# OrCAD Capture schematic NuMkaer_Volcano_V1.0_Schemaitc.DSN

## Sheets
1 Nu-Link2-Me: size A3; title: Nu-Link2-Me; rev: 1.0; company: CMHuang; note: Nu-Link2-Me
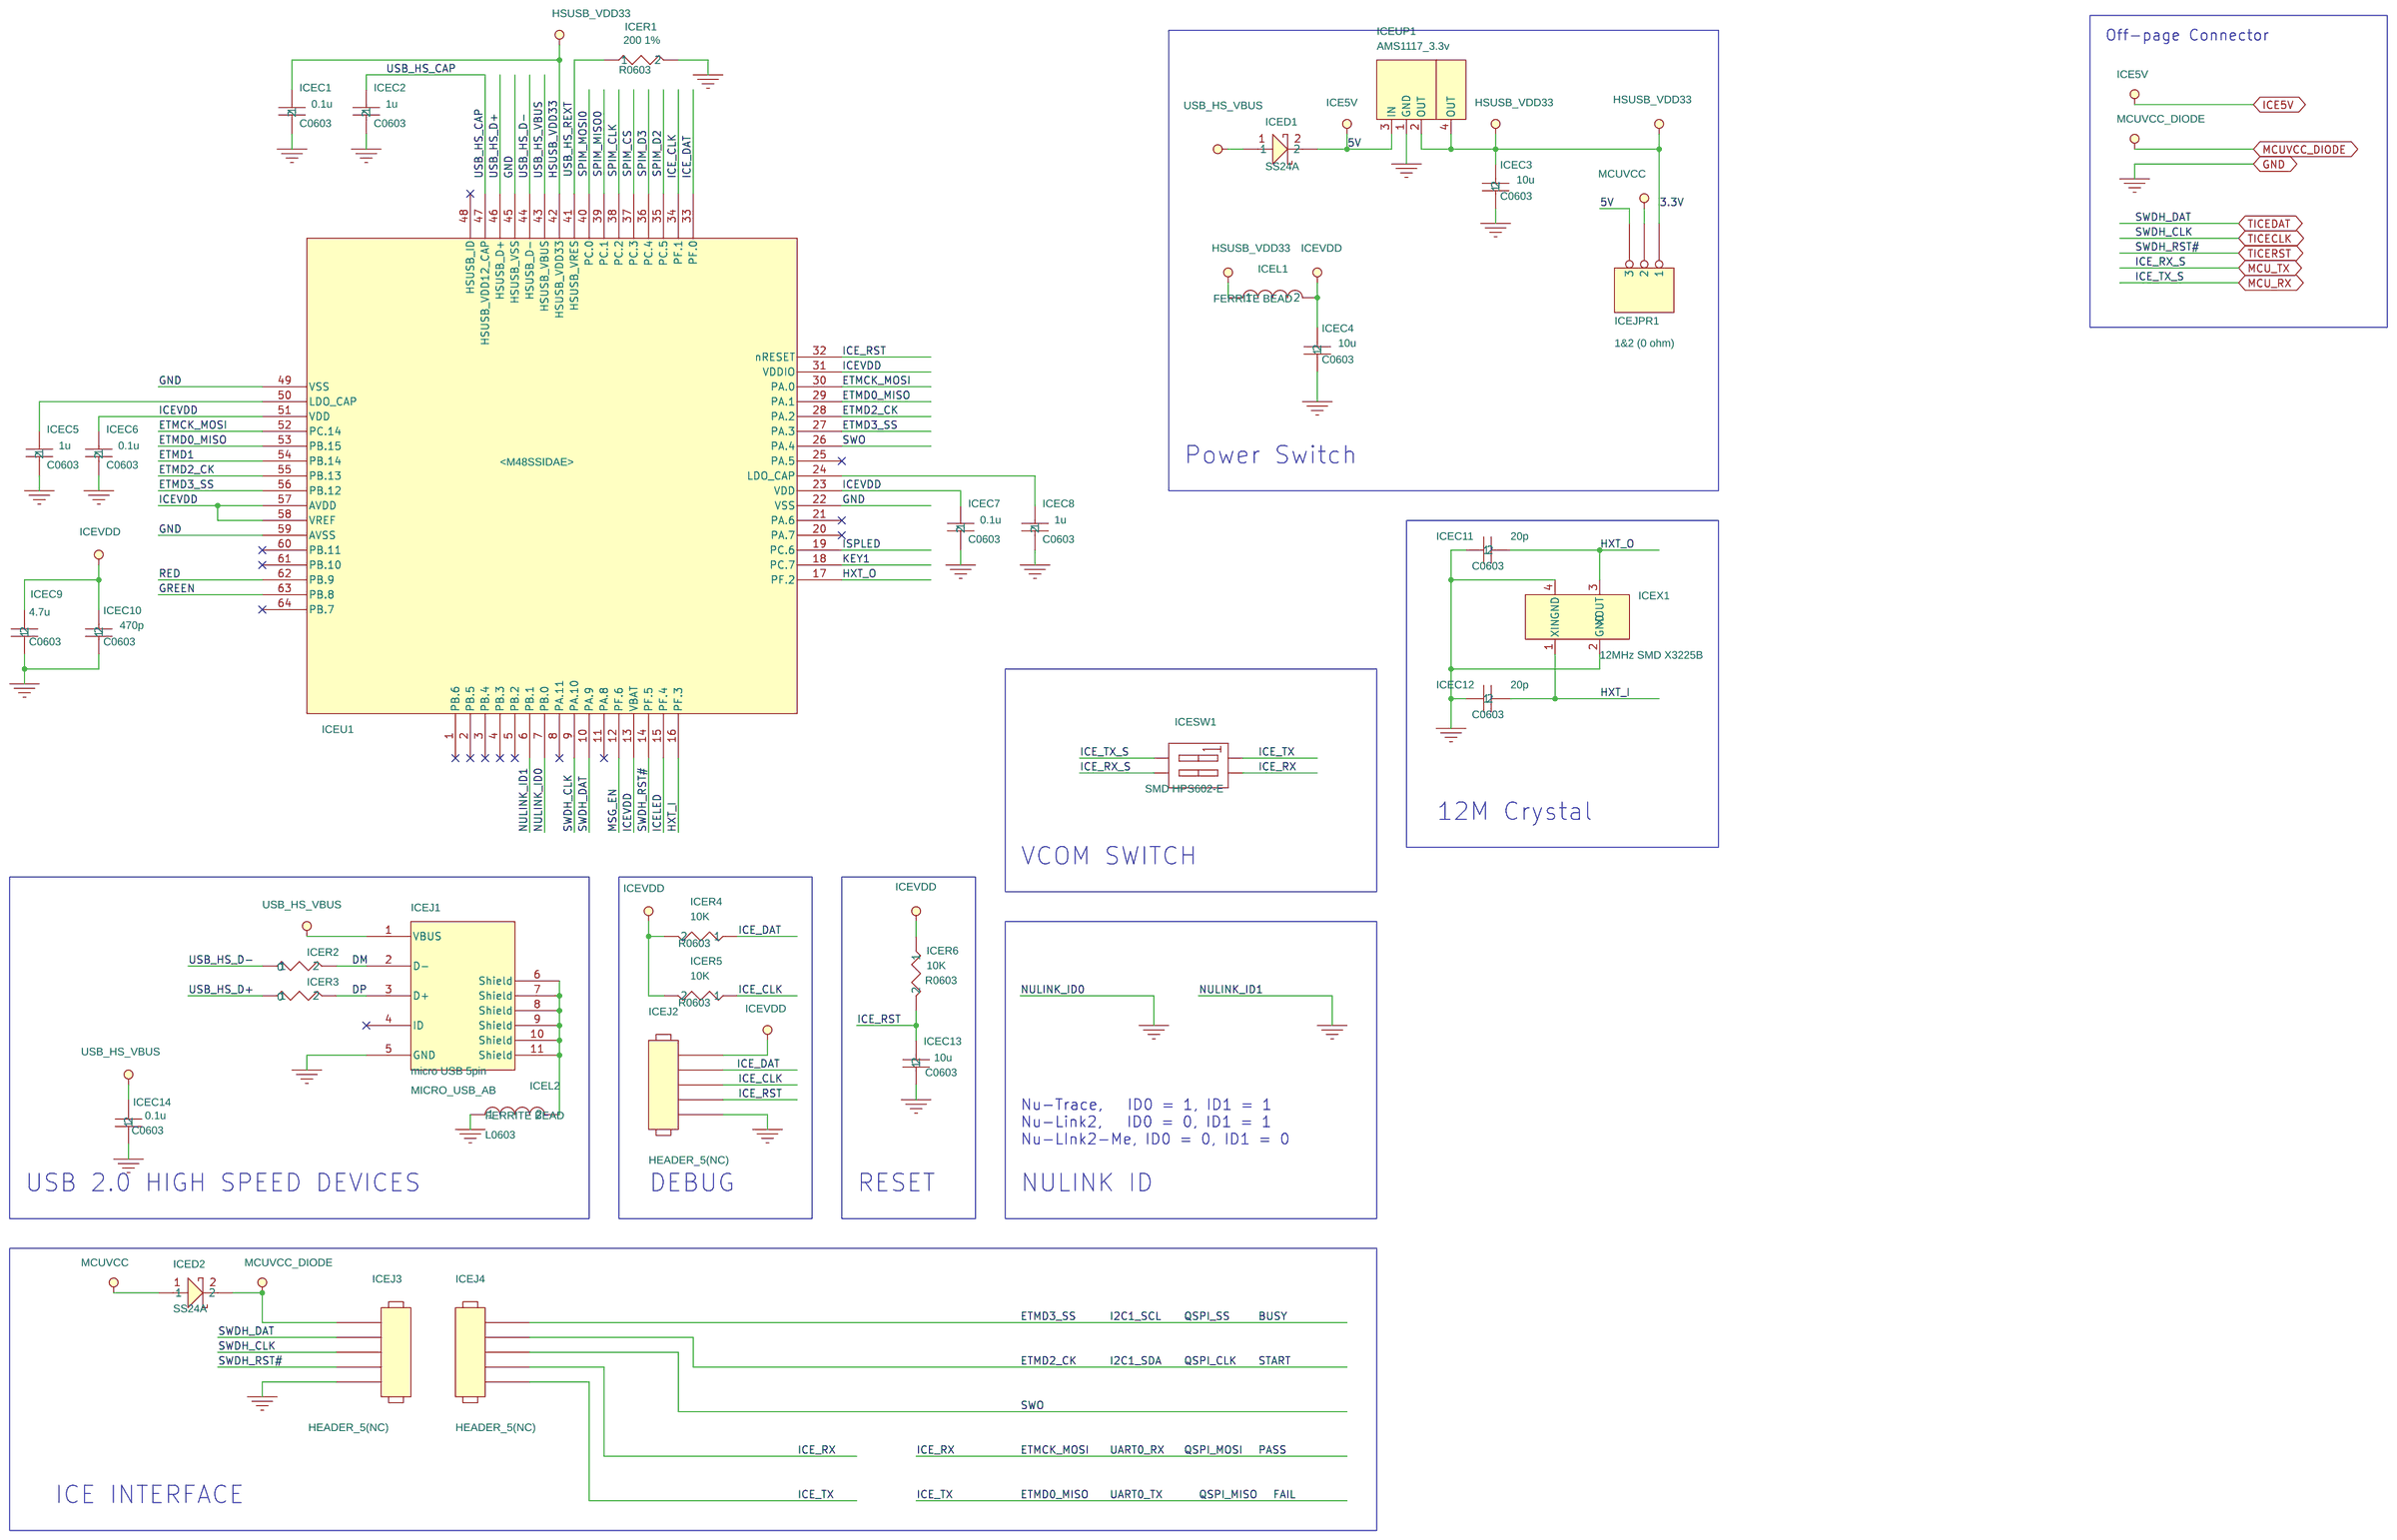
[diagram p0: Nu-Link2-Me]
2 M0A23EC1AC: size Custom; title: M0A23EC1AC; rev: v1.0; note: NuMaker-M0A23EC
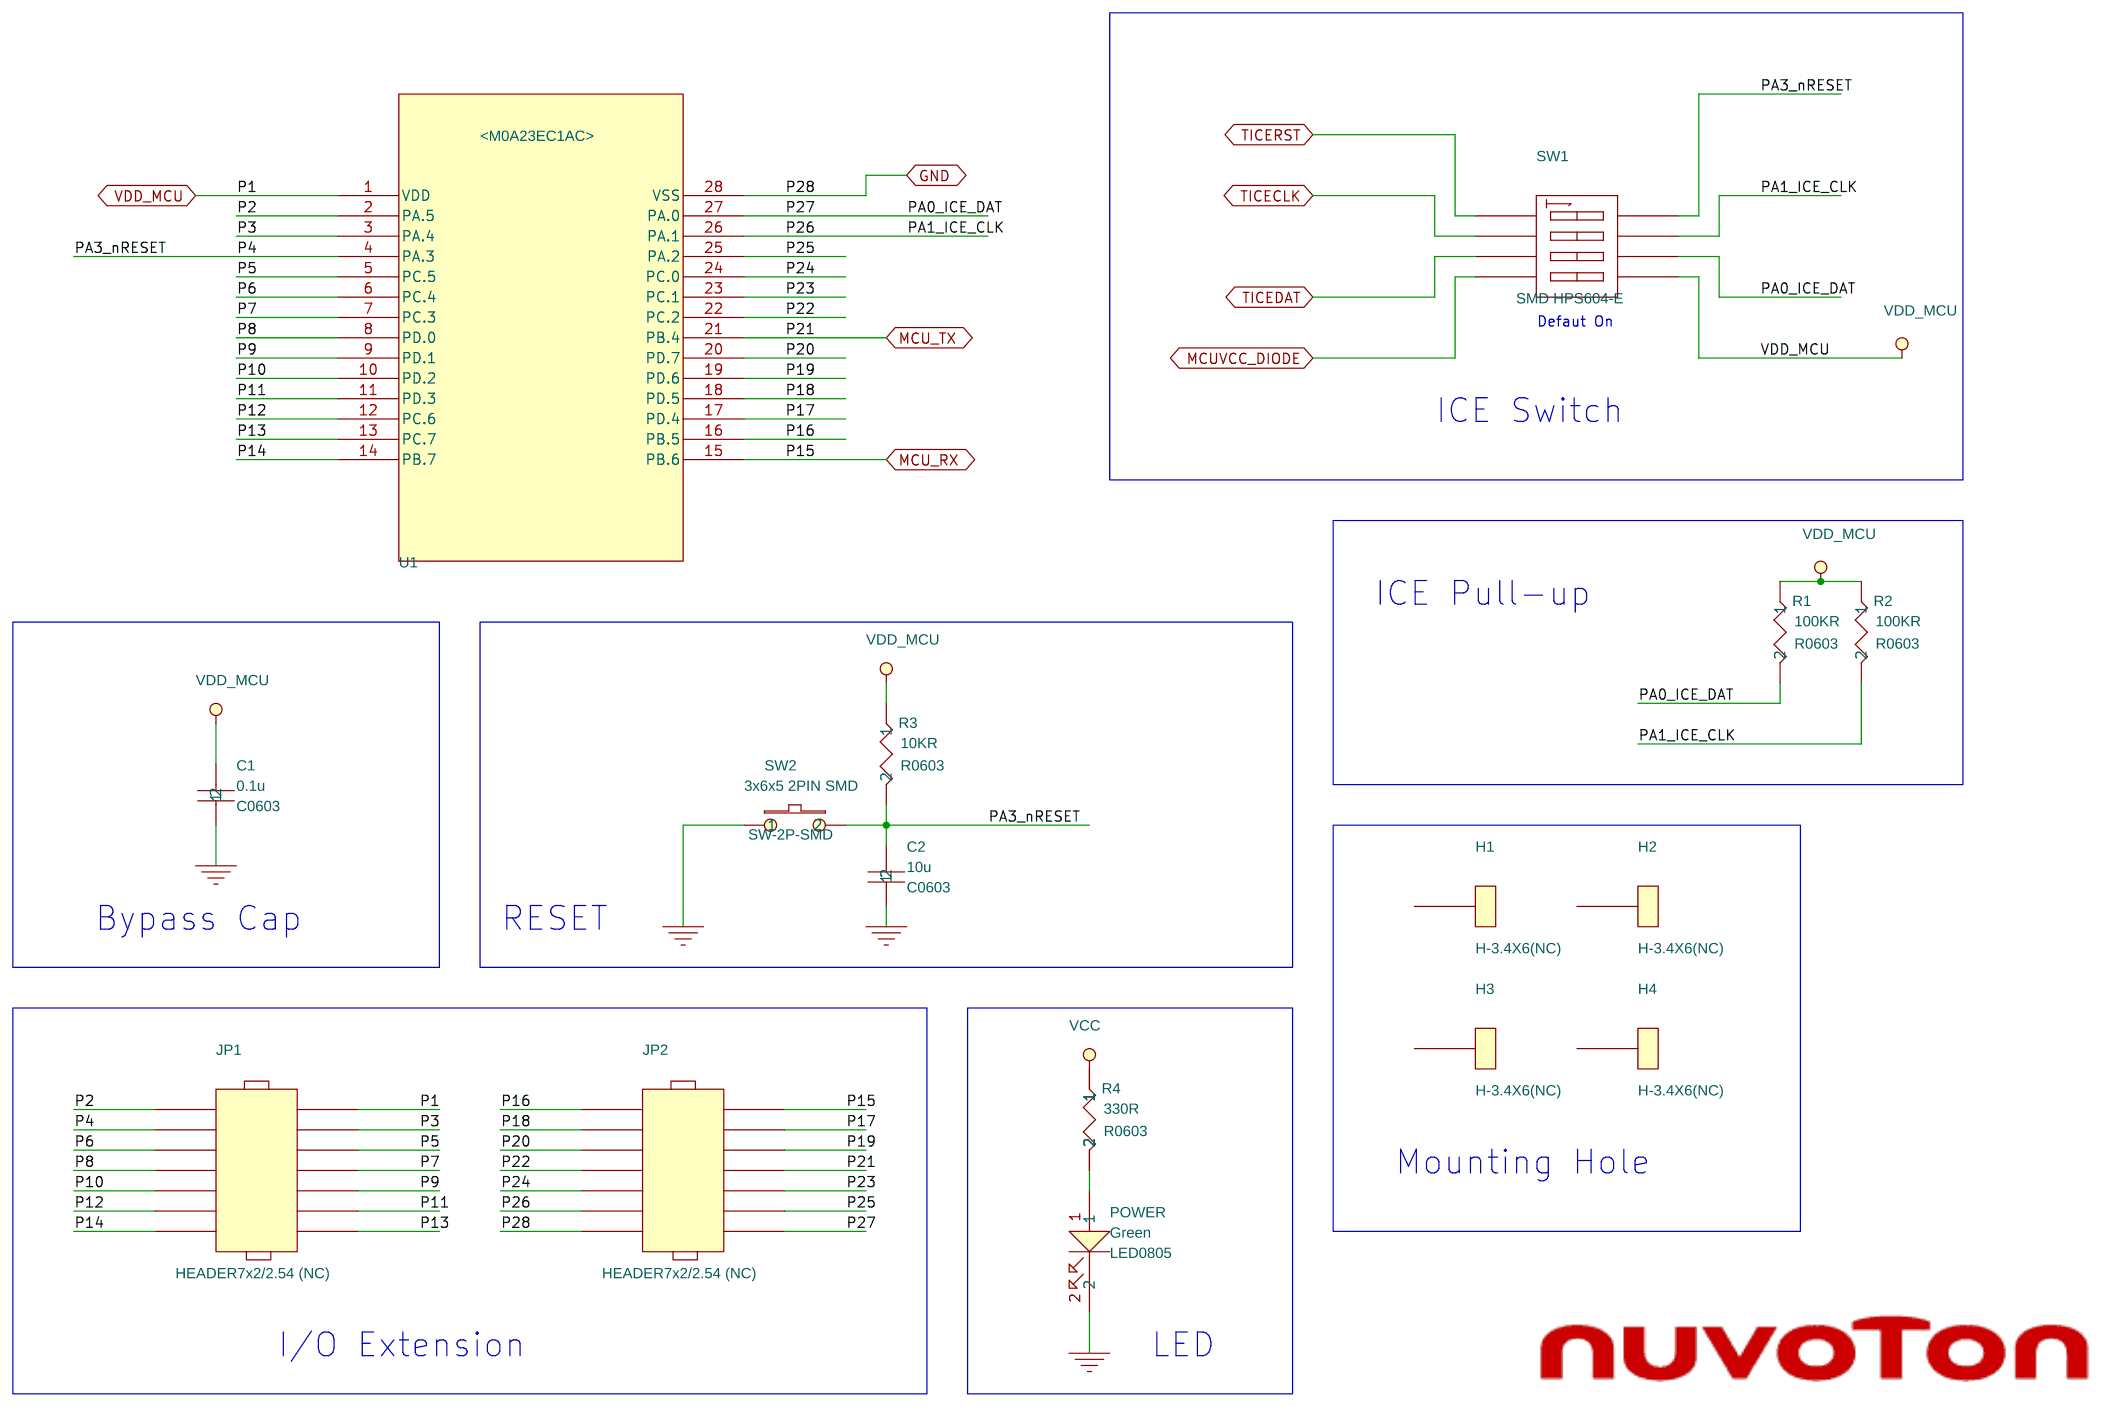
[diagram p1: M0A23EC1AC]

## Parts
sheet M0A23EC1AC
C1  0.1u  [C0603]
C2  10u  [C0603]
H1  H-3.4X6(NC)  [H-3.4X6]
H2  H-3.4X6(NC)  [H-3.4X6]
H3  H-3.4X6(NC)  [H-3.4X6]
H4  H-3.4X6(NC)  [H-3.4X6]
JP1  HEADER7x2/2.54 (NC)  [HEADER7x2/2.54]
JP2  HEADER7x2/2.54 (NC)  [HEADER7x2/2.54]
POWER  Green  [LED0805]
R1  100KR  [R0603]
R2  100KR  [R0603]
R3  10KR  [R0603]
R4  330R  [R0603]
SW1  SMD HPS604-E  [SW1X4]
SW2  3x6x5 2PIN SMD  [SW-2P-SMD]
U1  M0A23OC1AC  [MCU_TSSOP28_4.4X9.7MM]
sheet Nu-Link2-Me
ICEC1  0.1u  [C0603]
ICEC2  1u  [C0603]
ICEC3  10u  [C0603]
ICEC4  10u  [C0603]
ICEC5  1u  [C0603]
ICEC6  0.1u  [C0603]
ICEC7  0.1u  [C0603]
ICEC8  1u  [C0603]
ICEC9  4.7u  [C0603]
ICEC10  470p  [C0603]
ICEC11  20p  [C0603]
ICEC12  20p  [C0603]
ICEC13  10u  [C0603]
ICEC14  0.1u  [C0603]
ICED1  SS24A  [RB060L]
ICED2  SS24A  [RB060L]
ICEJ1  micro USB 5pin  [MICRO_USB_AB]
ICEJ2  HEADER_5(NC)  [HEADER5X1]
ICEJ3  HEADER_5(NC)  [HEADER5X1]
ICEJ4  HEADER_5(NC)  [HEADER5X1]
ICEJPR1  1&2 (0 ohm)  [R0603X2]
ICEL1  FERRITE BEAD  [L0603]
ICEL2  FERRITE BEAD  [L0603]
ICER1  200 1%  [R0603]
ICER2  0  [R0603]
ICER3  0  [R0603]
ICER4  10K  [R0603]
ICER5  10K  [R0603]
ICER6  10K  [R0603]
ICESW1  SMD HPS602-E  [SW1X2]
ICEU1  M48SSIDAE  [LQFP64_7x7_M48SSIDAE]
ICEUP1  AMS1117_3.3v  [SOT-223-1]
ICEX1  12MHz SMD X3225B  [CRYSTAL_SMD]

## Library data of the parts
C1 = CAP-C: Package: 0603; element_no: C0004
C2 = CAP-C_1: Package: 0603; element_no: C0006
H1-H4 = TEST_POINT
JP1 JP2 = HEADER_7X2_0
POWER = LED_0: Package: KP-2012; Vendor: Kingbright
ICER1 R1 = R_0_2: Package: 0603
ICER5 R2 = R_0_3: Package: 0603
ICER4 R3 = R_0: Package: 0603
ICER6 R4 = R_0_1: Package: 0603
SW1 = SW_DIP-4_SM
SW2 = SW_PUSHBUTTON_0
U1 = M0A23EC1AC_2: M023XC1AC: <M0A23EC1AC>
ICEC1 = CAP-C_9: Package: 0603; element_no: C0004
ICEC2 = CAP-C_10: Package: 0603; element_no: C0006
ICEC3 = CAP-C_3: Package: 0603
ICEC4 = CAP-C_11: Package: 0603
ICEC5 = CAP-C_12: Package: 0603; element_no: C0006
ICEC6 = CAP-C_2: Package: 0603; element_no: C0004
ICEC7 = CAP-C_5: Package: 0603; element_no: C0004
ICEC8 = CAP-C_6: Package: 0603; element_no: C0006
ICEC9 = CAP-C: Package: 0603
ICEC10 = CAP-C_7: Package: 0603
ICEC11 = CAP-C_4: Package: 0603
ICEC12 = CAP-C_13: Package: 0603
ICEC13 = CAP-C_8: Package: 0603; element_no: C0006
ICEC14 = CAP-C_1: Package: 0603; element_no: C0004
ICED1 = D_SS24A
ICED2 = D_SS24A_1
ICEJ1 = micro_USB_5pin_0
ICEJ2-ICEJ4 = HEADER_5
ICEJPR1 = HEADER_3
ICEL1 = FERRITE_BEAD
ICEL2 = FERRITE_BEAD_1
ICER2 = R_33
ICER3 = R_33_1
ICESW1 = SW_DIP-4_0
ICEU1 = M487SIDAE_0: M487SIDAE: <M48SSIDAE>
ICEUP1 = TO-247_Regulator_10
ICEX1 = Crystal_SMD_1

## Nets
3.3V: ICEC1.1 ICEC3.2 ICEJPR1.1 ICEL1.1 ICEU1.42(HSUSB_VDD33) ICEUP1.2(OUT) ICEUP1.4(OUT)
GND: C1.1 C2.1 ICEC1.2 ICEC2.2 ICEC3.1 ICEC4.1 ICEC5.2 ICEC6.2 ICEC7.2 ICEC8.2 ICEC9.1 ICEC10.1 ICEC11.1 ICEC12.1 ICEC13.1 ICEC14.1 ICEJ1.5(GND) ICEJ2.5 ICEJ3.5 ICEL2.1 ICER1.2 ICEU1.6(PB.1) ICEU1.7(PB.0) ICEU1.22(VSS) ICEU1.45(HSUSB_VSS) ICEU1.49(VSS) ICEU1.59(AVSS) ICEUP1.1(GND) ICEX1.2(GND) ICEX1.4(GND) JP2.14 POWER.2 SW2.1 U1.28(VSS)
VDD_MCU: C1.2 JP1.1 R1.1 R2.1 R3.1 R4.1 SW1.4(A4) U1.1(VDD)
BUSY: ICEJ4.1 ICEU1.27(PA.3) ICEU1.56(PB.12)
DM: ICEJ1.2(D-) ICER2.2
DP: ICEJ1.3(D+) ICER3.2
ETMCK_MOSI: ICEJ4.4 ICESW1.3(B1) ICEU1.30(PA.0) ICEU1.52(PC.14)
ETMD1: ICEU1.54(PB.14)
ETMD2_CK: ICEJ4.2 ICEU1.28(PA.2) ICEU1.55(PB.13)
GREEN: ICEU1.63(PB.8)
HXT_I: ICEC12.2 ICEU1.16(PF.3) ICEX1.1(XIN)
HXT_O: ICEC11.2 ICEU1.17(PF.2) ICEX1.3(XOUT)
ICE5V: ICED1.2 ICEJPR1.3 ICEUP1.3(IN)
ICE_CLK: ICEJ2.3 ICER5.1 ICEU1.34(PF.1)
ICE_DAT: ICEJ2.2 ICER4.1 ICEU1.33(PF.0)
ICE_RST: ICEC13.2 ICEJ2.4 ICER6.2 ICEU1.32(nRESET)
ICE_TX: ICEJ4.5 ICESW1.4(B2) ICEU1.29(PA.1) ICEU1.53(PB.15)
ICELED: ICEU1.15(PF.4)
ICEVDD: ICEC4.2 ICEC6.1 ICEC7.1 ICEC9.2 ICEC10.2 ICEJ2.1 ICEL1.2 ICER4.2 ICER5.2 ICER6.1 ICEU1.13(VBAT) ICEU1.23(VDD) ICEU1.31(VDDIO) ICEU1.51(VDD) ICEU1.57(AVDD) ICEU1.58(VREF)
ISPLED: ICEU1.19(PC.6)
KEY1: ICEU1.18(PC.7)
MCU_RX: ICESW1.1(A1) JP2.1 U1.15(PB.6)
MCU_TX: ICESW1.2(A2) JP2.7 U1.21(PB.4)
MCUVCC: ICED2.1 ICEJPR1.2
MCUVCC_DIODE: ICED2.2 ICEJ3.1 SW1.5(B4)
MSG_EN: ICEU1.12(PF.6)
P2: JP1.2 U1.2(PA.5)
P3: JP1.3 U1.3(PA.4)
P4: C2.2 JP1.4 R3.2 SW1.1(A1) SW2.2 U1.4(PA.3)
P5: JP1.5 U1.5(PC.5)
P6: JP1.6 U1.6(PC.4)
P7: JP1.7 U1.7(PC.3)
P8: JP1.8 U1.8(PD.0)
P9: JP1.9 U1.9(PD.1)
P10: JP1.10 U1.10(PD.2)
P11: JP1.11 U1.11(PD.3)
P12: JP1.12 U1.12(PC.6)
P13: JP1.13 U1.13(PC.7)
P14: JP1.14 U1.14(PB.7)
P16: JP2.2 U1.16(PB.5)
P17: JP2.3 U1.17(PD.4)
P18: JP2.4 U1.18(PD.5)
P19: JP2.5 U1.19(PD.6)
P20: JP2.6 U1.20(PD.7)
P22: JP2.8 U1.22(PC.2)
P23: JP2.9 U1.23(PC.1)
P24: JP2.10 U1.24(PC.0)
P25: JP2.11 U1.25(PA.2)
P26: JP2.12 R2.2 SW1.2(A2) U1.26(PA.1)
P27: JP2.13 R1.2 SW1.3(A3) U1.27(PA.0)
RED: ICEU1.62(PB.9)
SPIM_CLK: ICEU1.38(PC.2)
SPIM_CS: ICEU1.37(PC.3)
SPIM_D2: ICEU1.35(PC.5)
SPIM_D3: ICEU1.36(PC.4)
SPIM_MISO0: ICEU1.39(PC.1)
SPIM_MOSI0: ICEU1.40(PC.0)
SWO: ICEJ4.3 ICEU1.26(PA.4)
TICECLK: ICEJ3.3 ICEU1.9(PA.10) SW1.7(B2)
TICEDAT: ICEJ3.2 ICEU1.10(PA.9) SW1.6(B3)
TICERST: ICEJ3.4 ICEU1.14(PF.5) SW1.8(B1)
USB_HS_CAP: ICEC2.1 ICEU1.47(HSUSB_VDD12_CAP)
USB_HS_D+: ICER3.1 ICEU1.46(HSUSB_D+)
USB_HS_D-: ICER2.1 ICEU1.44(HSUSB_D-)
USB_HS_REXT: ICER1.1 ICEU1.41(HSUSB_VRES)
USB_HS_VBUS: ICEC14.2 ICED1.1 ICEJ1.1(VBUS) ICEU1.43(HSUSB_VBUS)
N16825237: POWER.1 R4.2
N16840819: ICEC8.1 ICEU1.24(LDO_CAP)
N16840960: ICEC5.1 ICEU1.50(LDO_CAP)
N17042369: ICEJ1.6(Shield) ICEJ1.7(Shield) ICEJ1.8(Shield) ICEJ1.9(Shield) ICEJ1.10(Shield) ICEJ1.11(Shield) ICEL2.2

Not connected (* = marked no-connect by the designer): H1 1; H2 1; H3 1; H4 1; ICEJ1 4(ID)*; ICEU1 1(PB.6)* 2(PB.5)* 3(PB.4)* 4(PB.3)* 5(PB.2)* 8(PA.11)* 11(PA.8)* 20(PA.7)* 21(PA.6)* 25(PA.5)* 48(HSUSB_ID)* 60(PB.11)* 61(PB.10)* 64(PB.7)*

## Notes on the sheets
sheet 1
- Off-page Connector
- Power Switch
- 12M Crystal
- VCOM SWITCH
- Nu-Trace,   ID0 = 1, ID1 = 1
  Nu-Link2,   ID0 = 0, ID1 = 1
  Nu-LInk2-Me, ID0 = 0, ID1 = 0
- USB 2.0 HIGH SPEED DEVICES
- DEBUG
- RESET
- NULINK ID
- ICE INTERFACE
sheet 2
- Defaut On
- ICE Switch
- ICE Pull-up
- Bypass Cap
- RESET
- Mounting Hole
- I/O Extension
- LED
